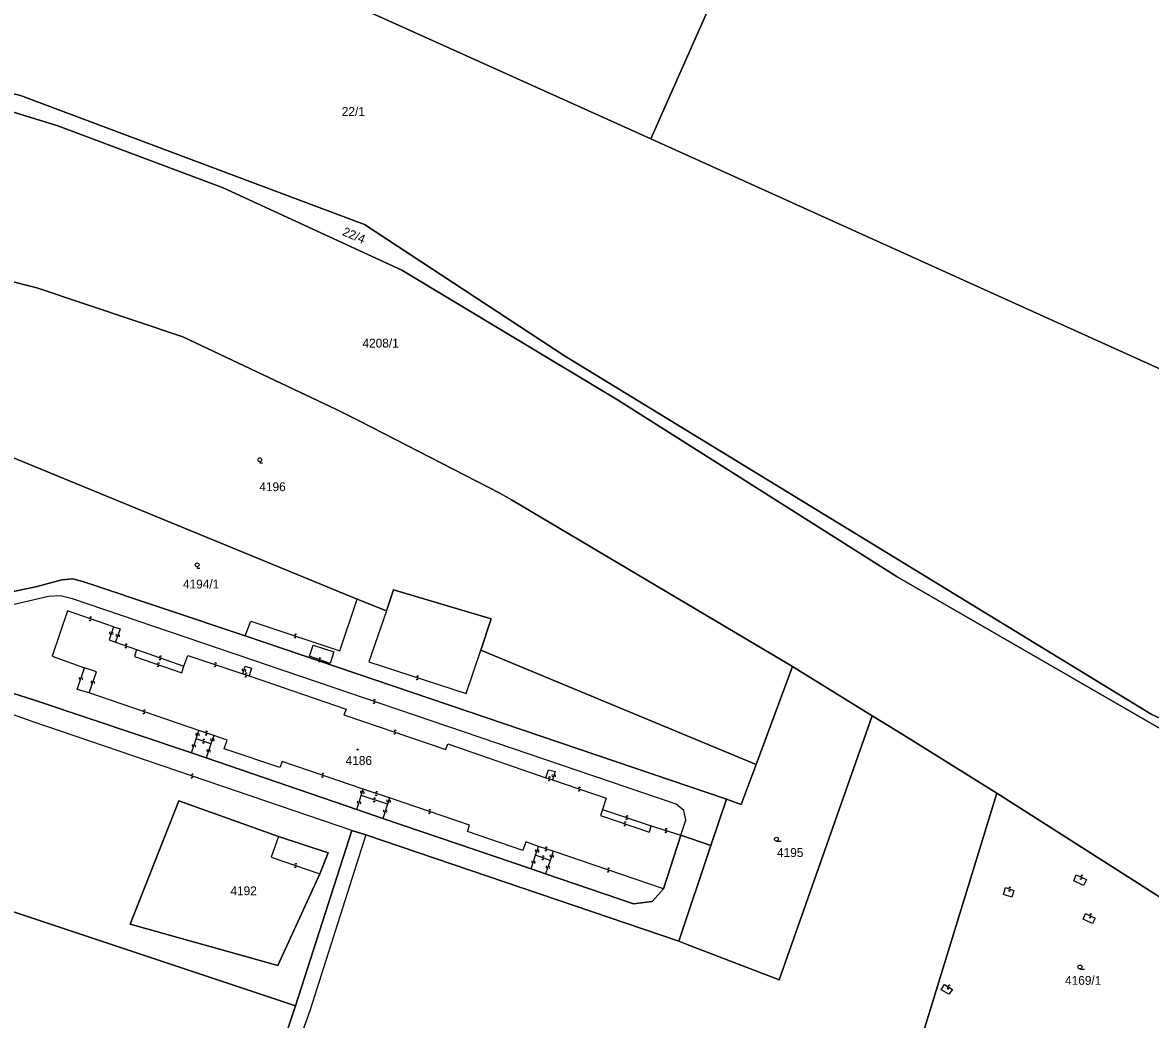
# Model space of a CAD drawing. Extents: x -598233 to -596890, y -1157848 to -1156431.
# Drawn here: x -597840.5 to -597624.3, y -1157433.9 to -1157242.7 of the extents above; entities that cross this region are included whole.
import ezdxf

# ---------------------------------------------------------------- set-up
doc = ezdxf.new("R2010")
doc.units = 0
for name, color, linetype in [('Level 1', 7, 'Continuous'), ('Level 13', 7, 'Continuous'), ('Level 3', 7, 'Continuous'), ('Level 4', 7, 'Continuous'), ('Level 5', 7, 'Continuous'), ('Level 60', 7, 'Continuous'), ('Vrstva 54', 7, 'Continuous'), ('Vrstva 60', 7, 'Continuous')]:
    doc.layers.add(name, color=color, linetype=linetype)

msp = doc.modelspace()

# ---------------------------------------------------------------- linework, layer by layer
at = {"layer": 'Level 1'}
for points in [[(-597802.39, -1157227.84), (-597776.1, -1157174.66), (-597757.16, -1157192.27), (-597734.08, -1157200.94), (-597717.33, -1157206.86), (-597697.73, -1157214.64), (-597720.07, -1157265.02)], [(-597720.07, -1157265.02), (-597802.39, -1157227.84)], [(-597939.77, -1157233.9), (-597929.67, -1157236.56), (-597923.63, -1157238.02), (-597882.54, -1157247.95), (-597875.91, -1157249.55), (-597833.74, -1157262.53), (-597802.08, -1157274.42), (-597767.8, -1157290.17), (-597726.42, -1157315.06), (-597672.84, -1157349.01), (-597621.47, -1157378.62), (-597620.65, -1157379.11), (-597584.75, -1157400.18), (-597549.68, -1157428.4), (-597544.41, -1157433.47), (-597538.53, -1157436.14), (-597519.06, -1157444.97), (-597467.58, -1157472.78), (-597426.75, -1157494.36), (-597424.47, -1157501.56)], [(-597881.96, -1157245.26), (-597876.93, -1157246.47), (-597851.3, -1157254.2), (-597840.9, -1157256.69), (-597774.98, -1157281.45), (-597736.6, -1157306.64), (-597624.12, -1157375.33), (-597619.87, -1157377.31)], [(-597882.54, -1157247.95), (-597875.91, -1157249.55), (-597833.74, -1157262.53), (-597802.08, -1157274.42), (-597767.8, -1157290.17), (-597726.42, -1157315.06), (-597672.84, -1157349.01), (-597621.47, -1157378.62), (-597620.65, -1157379.11)], [(-597594.92, -1157321.55), (-597720.07, -1157265.02)], [(-597927.09, -1157273.98), (-597877.78, -1157283.48), (-597837.79, -1157293.58), (-597809.77, -1157302.98), (-597780.3, -1157316.91), (-597775.85, -1157319.11), (-597749.01, -1157332.97), (-597746.79, -1157334.23), (-597692.89, -1157366.17)], [(-597926.42, -1157291.58), (-597776.35, -1157353.26)], [(-597876.22, -1157362.87), (-597873.55, -1157361.33), (-597870.19, -1157359.57), (-597867.07, -1157358.08), (-597864.1, -1157356.88), (-597860.64, -1157355.76), (-597857.5, -1157354.95), (-597837.95, -1157350.9), (-597832.96, -1157349.57), (-597830.88, -1157349.39), (-597828.79, -1157349.95), (-597797.85, -1157360.32)], [(-597776.35, -1157353.26), (-597770.76, -1157355.54)], [(-597770.76, -1157355.54), (-597769.38, -1157351.46), (-597750.67, -1157357.07), (-597752.67, -1157363.06)], [(-597797.85, -1157360.32), (-597705.57, -1157391.65)], [(-597752.67, -1157363.06), (-597699.85, -1157384.95)], [(-597808.11, -1157382.76), (-597838.2, -1157372.62), (-597845.13, -1157370.45), (-597867.55, -1157364.93)], [(-597699.85, -1157384.95), (-597692.89, -1157366.17)], [(-597692.89, -1157366.17), (-597677.64, -1157375.67)], [(-597677.64, -1157375.67), (-597695.43, -1157426.25), (-597712.77, -1157419.6), (-597714.69, -1157418.85)], [(-597677.64, -1157375.67), (-597672.9, -1157378.55), (-597653.75, -1157390.49)], [(-597805.31, -1157383.72), (-597808.11, -1157382.76)], [(-597776.45, -1157393.59), (-597805.31, -1157383.72)], [(-597699.85, -1157384.95), (-597702.71, -1157392.63), (-597705.57, -1157391.65)], [(-597791.44, -1157398.75), (-597810.55, -1157391.95), (-597819.87, -1157415.56), (-597791.6, -1157423.52), (-597783.54, -1157405.96)], [(-597705.57, -1157391.65), (-597708.54, -1157400.5)], [(-597667.82, -1157436.45), (-597653.75, -1157390.49)], [(-597653.75, -1157390.49), (-597620.55, -1157411.64), (-597581.5, -1157434.85), (-597556.28, -1157449.32)], [(-597771.45, -1157395.32), (-597776.45, -1157393.59)], [(-597743.02, -1157405), (-597771.45, -1157395.32)], [(-597791.44, -1157398.75), (-597781.95, -1157401.92), (-597783.54, -1157405.96)], [(-597788.17, -1157431.27), (-597777.36, -1157397.61)], [(-597774.67, -1157398.49), (-597777.36, -1157397.61)], [(-597774.67, -1157398.49), (-597714.69, -1157418.85)], [(-597714.3, -1157398.55), (-597717.66, -1157408.79)], [(-597708.54, -1157400.5), (-597714.3, -1157398.55)], [(-597708.54, -1157400.5), (-597714.69, -1157418.85)], [(-597740.24, -1157405.97), (-597743.02, -1157405)], [(-597740.24, -1157405.97), (-597723.35, -1157411.67), (-597719.83, -1157411.25), (-597717.66, -1157408.79)], [(-597788.17, -1157431.27), (-597855.38, -1157408.86)], [(-597788.17, -1157431.27), (-597800.65, -1157468.66), (-597811.31, -1157496.58)]]:
    msp.add_lwpolyline(points, dxfattribs=at)
at = {"layer": 'Level 13'}
for centre, start, end in [((-597827.57, -1157357.19), 198.2569, 70.3549), ((-597827.45, -1157356.85), 18.0424, 250.6324), ((-597823.69, -1157359.74), 109.1385, 341.7285), ((-597823.35, -1157359.86), 289.353, 161.451), ((-597822.42, -1157360.18), 108.8588, 341.4488), ((-597822.08, -1157360.3), 289.0732, 161.1712), ((-597820.62, -1157362.06), 17.4822, 249.5801), ((-597788.28, -1157360.49), 198.8138, 71.4038), ((-597788.16, -1157360.15), 19.0283, 251.1263), ((-597820.74, -1157362.4), 197.2677, 69.8577), ((-597814.07, -1157364.37), 18.2059, 250.3039), ((-597814.56, -1157366.01), 198.1016, 70.6916), ((-597814.44, -1157365.67), 18.3161, 250.4141), ((-597814.19, -1157364.71), 197.9915, 70.5815), ((-597803.63, -1157366.02), 198.5277, 71.1177), ((-597803.51, -1157365.68), 18.7421, 250.8401), ((-597783.6, -1157365.07), 198.1601, 70.2581), ((-597783.48, -1157364.73), 17.9456, 250.5356), ((-597829.51, -1157368.44), 108.7727, 340.8707), ((-597829.17, -1157368.56), 288.5582, 161.1482), ((-597798.25, -1157366.83), 109.6422, 341.7402), ((-597797.89, -1157366.95), 289.4278, 162.0178), ((-597797.74, -1157367.99), 200.5439, 73.1339), ((-597797.64, -1157367.63), 20.7583, 252.8563), ((-597764.87, -1157368.51), 199.1111, 71.7011), ((-597764.75, -1157368.17), 19.3255, 251.4235), ((-597827.2, -1157369.17), 108.3427, 340.4407), ((-597826.86, -1157369.29), 288.1283, 160.7183), ((-597773.04, -1157372.73), 18.3499, 250.9399), ((-597817.27, -1157375.03), 198.4084, 70.5064), ((-597817.15, -1157374.69), 18.194, 250.784), ((-597773.16, -1157373.07), 198.5644, 70.6624), ((-597807.12, -1157379.19), 109.1599, 341.2579), ((-597806.78, -1157379.31), 288.9454, 161.5354), ((-597805.34, -1157379.13), 198.6346, 70.7326), ((-597805.22, -1157378.79), 18.4202, 251.0102), ((-597769.18, -1157378.92), 198.3372, 70.9272), ((-597769.06, -1157378.58), 18.5516, 250.6496), ((-597807.83, -1157381.34), 108.9378, 341.0358), ((-597807.49, -1157381.46), 288.7233, 161.3133), ((-597805.86, -1157380.68), 198.5107, 70.6087), ((-597805.74, -1157380.34), 18.2962, 250.8862), ((-597804.29, -1157380.15), 108.2809, 340.8709), ((-597803.95, -1157380.27), 288.4954, 160.5934), ((-597805.02, -1157382.3), 108.5346, 341.1247), ((-597804.68, -1157382.42), 288.7491, 160.8471), ((-597808.08, -1157387.35), 198.5798, 70.6778), ((-597807.96, -1157387.01), 18.3653, 250.9553), ((-597783.03, -1157387.21), 198.4962, 70.5942), ((-597782.91, -1157386.87), 18.2818, 250.8718), ((-597739.59, -1157387.88), 200.5439, 73.1339), ((-597739.49, -1157387.52), 20.7583, 252.8563), ((-597738.84, -1157387.06), 109.2796, 341.8696), ((-597738.49, -1157387.18), 289.494, 161.592), ((-597775.56, -1157390.26), 110.7583, 342.8563), ((-597733.84, -1157389.85), 197.9901, 70.5801), ((-597733.72, -1157389.51), 18.2045, 250.3025), ((-597776.18, -1157392.2), 109.0671, 341.1651), ((-597775.84, -1157392.32), 288.8527, 161.4427), ((-597775.2, -1157390.36), 290.5439, 163.1339), ((-597773.11, -1157391.92), 199.348, 71.446), ((-597772.99, -1157391.58), 19.1336, 251.7236), ((-597772.74, -1157390.71), 198.8355, 70.9335), ((-597772.62, -1157390.37), 18.6211, 251.2111), ((-597770.52, -1157391.92), 109.8865, 342.4765), ((-597770.16, -1157392.04), 290.101, 162.199), ((-597771.16, -1157393.88), 108.6608, 341.2508), ((-597770.82, -1157394), 288.8753, 160.9733), ((-597762.54, -1157394.16), 198.6027, 70.7007), ((-597762.42, -1157393.82), 18.3883, 250.9783), ((-597725.09, -1157396.53), 198.5039, 71.0939), ((-597724.97, -1157396.19), 18.7184, 250.8164), ((-597724.72, -1157395.33), 198.7049, 71.2949), ((-597724.6, -1157394.99), 18.9193, 251.0173), ((-597717.21, -1157397.8), 199.2678, 71.8578), ((-597717.09, -1157397.46), 19.4823, 251.5803), ((-597740.1, -1157400.99), 18.8458, 251.4358), ((-597742.03, -1157401.48), 108.7346, 340.8326), ((-597741.69, -1157401.6), 288.5202, 161.1102), ((-597740.81, -1157403.05), 197.5885, 69.6865), ((-597740.69, -1157402.71), 17.374, 249.964), ((-597740.22, -1157401.33), 199.0602, 71.1582), ((-597739.23, -1157402.44), 108.3336, 340.9236), ((-597738.89, -1157402.56), 288.548, 160.646), ((-597788.24, -1157404.52), 198.0224, 70.6124), ((-597788.12, -1157404.18), 18.2368, 250.3348), ((-597742.75, -1157403.63), 108.8067, 340.9047), ((-597742.41, -1157403.75), 288.5922, 161.1822), ((-597739.97, -1157404.62), 108.3921, 340.9821), ((-597739.63, -1157404.74), 288.6066, 160.7046), ((-597728.27, -1157405.37), 198.6044, 70.7024), ((-597728.15, -1157405.03), 18.39, 250.98), ((-597637.6, -1157406.77), 193.0879, 65.6779), ((-597637.44, -1157406.43), 13.3024, 245.4004), ((-597651.33, -1157409.05), 197.7738, 70.3638), ((-597651.21, -1157408.71), 17.9882, 250.0862), ((-597635.7, -1157413.82), 11.672, 243.77), ((-597635.86, -1157414.16), 191.4575, 64.0475), ((-597663.08, -1157427.81), 185.5926, 58.1826), ((-597662.88, -1157427.49), 5.807, 237.905)]:
    msp.add_arc(centre, 0.184, start, end, dxfattribs=at)
at = {"layer": 'Level 3'}
for points in [[(-597714.3, -1157398.55), (-597713.34, -1157395.67), (-597713.73, -1157393.79), (-597715.23, -1157392.61), (-597830.97, -1157353.19), (-597833.29, -1157352.62), (-597835.57, -1157352.76), (-597856.68, -1157357.71), (-597862.88, -1157359.71), (-597868.02, -1157361.9), (-597868.88, -1157362.47), (-597869.18, -1157363.46), (-597868.86, -1157364.34), (-597867.55, -1157364.93)], [(-597797.85, -1157360.32), (-597796.77, -1157357.48), (-597779.67, -1157363.15), (-597776.35, -1157353.26)], [(-597823.11, -1157358.55), (-597831.91, -1157355.5), (-597834.84, -1157364.2), (-597828.64, -1157366.42)], [(-597770.76, -1157355.54), (-597774.14, -1157365.3), (-597755.48, -1157371.38), (-597752.67, -1157363.06)], [(-597823.11, -1157358.55), (-597823.92, -1157361.04), (-597822.67, -1157361.51)], [(-597823.11, -1157358.55), (-597821.83, -1157358.97), (-597822.67, -1157361.51)], [(-597822.67, -1157361.51), (-597818.69, -1157362.95)], [(-597818.69, -1157362.95), (-597819.04, -1157364.27), (-597809.95, -1157367.41), (-597809.57, -1157366.12)], [(-597818.69, -1157362.95), (-597809.57, -1157366.12)], [(-597809.57, -1157366.12), (-597808.84, -1157364.07), (-597798.31, -1157367.62)], [(-597784.8, -1157362.06), (-597780.86, -1157363.39), (-597781.56, -1157365.59), (-597785.52, -1157364.21), (-597784.8, -1157362.06)], [(-597798.31, -1157367.62), (-597797.84, -1157366.15), (-597796.6, -1157366.52), (-597797.07, -1157367.99)], [(-597827.73, -1157371.25), (-597830.04, -1157370.58), (-597828.64, -1157366.42)], [(-597827.73, -1157371.25), (-597826.34, -1157367.22), (-597828.64, -1157366.42)], [(-597798.31, -1157367.62), (-597797.07, -1157367.99)], [(-597797.07, -1157367.99), (-597778.49, -1157374.34), (-597778.89, -1157375.42), (-597759.35, -1157382.08), (-597758.97, -1157381), (-597740.16, -1157387.52)], [(-597806.69, -1157378.48), (-597827.73, -1157371.25)], [(-597777.36, -1157397.61), (-597838.69, -1157376.74), (-597842.27, -1157375.46)], [(-597807.2, -1157380.03), (-597806.69, -1157378.48)], [(-597803.86, -1157379.44), (-597806.69, -1157378.48)], [(-597808.11, -1157382.76), (-597807.2, -1157380.03)], [(-597804.39, -1157380.99), (-597807.2, -1157380.03)], [(-597804.39, -1157380.99), (-597805.31, -1157383.72)], [(-597803.86, -1157379.44), (-597804.39, -1157380.99)], [(-597775.2, -1157389.69), (-597790.73, -1157384.38), (-597791.19, -1157385.53), (-597801.84, -1157381.96), (-597801.27, -1157380.32), (-597803.86, -1157379.44)], [(-597740.16, -1157387.52), (-597739.68, -1157385.97), (-597738.42, -1157386.34), (-597738.92, -1157387.89)], [(-597740.16, -1157387.52), (-597738.92, -1157387.89)], [(-597738.92, -1157387.89), (-597728.65, -1157391.46), (-597729.32, -1157393.6)], [(-597775.57, -1157390.93), (-597775.2, -1157389.69)], [(-597770.16, -1157391.38), (-597775.2, -1157389.69)], [(-597776.45, -1157393.59), (-597775.57, -1157390.93)], [(-597770.53, -1157392.57), (-597775.57, -1157390.93)], [(-597770.16, -1157391.38), (-597770.53, -1157392.57)], [(-597741.57, -1157400.69), (-597744.01, -1157399.83), (-597744.6, -1157401.47), (-597755.22, -1157397.83), (-597754.8, -1157396.6), (-597770.16, -1157391.38)], [(-597770.53, -1157392.57), (-597771.45, -1157395.32)], [(-597729.32, -1157393.6), (-597729.73, -1157394.78), (-597720.34, -1157397.95), (-597720, -1157396.71)], [(-597729.32, -1157393.6), (-597720, -1157396.71)], [(-597774.67, -1157398.49), (-597785.43, -1157432.18), (-597799.88, -1157472.24), (-597820.65, -1157539.16)], [(-597791.44, -1157398.75), (-597792.82, -1157402.74), (-597783.54, -1157405.96)], [(-597720, -1157396.71), (-597714.3, -1157398.55)], [(-597742.14, -1157402.38), (-597741.57, -1157400.69)], [(-597738.76, -1157401.62), (-597741.57, -1157400.69)], [(-597743.02, -1157405), (-597742.14, -1157402.38)], [(-597739.36, -1157403.38), (-597742.14, -1157402.38)], [(-597738.76, -1157401.62), (-597739.36, -1157403.38)], [(-597717.66, -1157408.79), (-597738.76, -1157401.62)], [(-597739.36, -1157403.38), (-597740.24, -1157405.97)], [(-597638.5, -1157406.16), (-597636.53, -1157407.04), (-597637.09, -1157408.15), (-597638.96, -1157407.28), (-597638.5, -1157406.16)], [(-597652.08, -1157408.59), (-597650.46, -1157409.16), (-597650.86, -1157410.42), (-597652.46, -1157409.93), (-597652.08, -1157408.59)], [(-597636.72, -1157413.54), (-597634.85, -1157414.44), (-597635.38, -1157415.47), (-597637.17, -1157414.61), (-597636.72, -1157413.54)], [(-597663.74, -1157427.18), (-597662.21, -1157428.12), (-597662.9, -1157429.04), (-597664.38, -1157428.17), (-597663.74, -1157427.18)]]:
    msp.add_lwpolyline(points, dxfattribs=at)
at = {"layer": 'Level 5'}
for p, q in [((-597695.98, -1157399.67), (-597695.1, -1157399.67)), ((-597637.79, -1157424.19), (-597636.92, -1157424.19))]:
    msp.add_line(p, q, dxfattribs=at)
for points in [[(-597795.02, -1157326.91), (-597795.02, -1157327.16), (-597794.52, -1157327.16)], [(-597807.04, -1157347.06), (-597807.04, -1157347.31), (-597806.54, -1157347.31)]]:
    msp.add_lwpolyline(points, dxfattribs=at)
for centre, radius in [((-597795.02, -1157326.54), 0.375), ((-597807.04, -1157346.69), 0.375), ((-597776.27, -1157382.11), 0.09), ((-597776.27, -1157382.11), 0.0521), ((-597695.98, -1157399.29), 0.375), ((-597637.79, -1157423.81), 0.375)]:
    msp.add_circle(centre, radius, dxfattribs=at)
at = {"layer": 'Level 60'}
for points in [[(-597553.97, -1157115.98), (-597451.73, -1157167.37), (-597517.72, -1157209.12), (-597524.08, -1157216.07), (-597544.75, -1157236.3), (-597553.08, -1157244.43), (-597572.6, -1157270.07), (-597583.83, -1157284.82), (-597594.92, -1157321.55), (-597720.07, -1157265.02), (-597697.73, -1157214.64), (-597717.33, -1157206.86), (-597734.08, -1157200.94), (-597757.16, -1157192.27), (-597776.1, -1157174.66), (-597802.39, -1157227.84), (-597822.9, -1157218.58), (-597805.12, -1157122.39)], [(-597805.12, -1157122.39), (-597822.9, -1157218.58), (-597802.39, -1157227.84), (-597720.07, -1157265.02), (-597594.92, -1157321.55), (-597604.05, -1157339.11), (-597605.14, -1157343.41), (-597619.87, -1157377.31), (-597624.12, -1157375.33), (-597736.6, -1157306.64), (-597774.98, -1157281.45), (-597840.9, -1157256.69), (-597851.3, -1157254.2), (-597876.93, -1157246.47), (-597881.96, -1157245.26), (-597923.53, -1157235.13), (-597922.9, -1157217.48), (-597918.43, -1157192.25), (-597917.62, -1157187.34), (-597920.96, -1157183.45), (-597938.58, -1157148.02), (-597940.99, -1157134.33)], [(-597875.91, -1157249.55), (-597833.74, -1157262.53), (-597802.08, -1157274.42), (-597767.8, -1157290.17), (-597726.42, -1157315.06), (-597672.84, -1157349.01), (-597621.47, -1157378.62)], [(-597620.55, -1157411.64), (-597653.75, -1157390.49), (-597672.9, -1157378.55), (-597677.64, -1157375.67), (-597692.89, -1157366.17), (-597746.79, -1157334.23), (-597749.01, -1157332.97), (-597775.85, -1157319.11), (-597780.3, -1157316.91), (-597809.77, -1157302.98), (-597837.79, -1157293.58), (-597877.78, -1157283.48)], [(-597926.42, -1157291.58), (-597776.35, -1157353.26), (-597770.76, -1157355.54), (-597769.38, -1157351.46), (-597750.67, -1157357.07), (-597752.67, -1157363.06), (-597699.85, -1157384.95), (-597702.71, -1157392.63), (-597705.57, -1157391.65), (-597797.85, -1157360.32), (-597828.79, -1157349.95), (-597830.88, -1157349.39), (-597832.96, -1157349.57), (-597837.95, -1157350.9), (-597857.5, -1157354.95)], [(-597857.5, -1157354.95), (-597837.95, -1157350.9), (-597832.96, -1157349.57), (-597830.88, -1157349.39), (-597828.79, -1157349.95), (-597797.85, -1157360.32), (-597705.57, -1157391.65), (-597708.54, -1157400.5), (-597714.3, -1157398.55), (-597717.66, -1157408.79), (-597719.83, -1157411.25), (-597723.35, -1157411.67), (-597740.24, -1157405.97), (-597743.02, -1157405), (-597771.45, -1157395.32), (-597776.45, -1157393.59), (-597805.31, -1157383.72), (-597808.11, -1157382.76), (-597838.2, -1157372.62), (-597845.13, -1157370.45)], [(-597845.13, -1157370.45), (-597838.2, -1157372.62), (-597808.11, -1157382.76), (-597805.31, -1157383.72), (-597776.45, -1157393.59), (-597771.45, -1157395.32), (-597743.02, -1157405), (-597740.24, -1157405.97), (-597723.35, -1157411.67), (-597719.83, -1157411.25), (-597717.66, -1157408.79), (-597714.3, -1157398.55), (-597708.54, -1157400.5), (-597714.69, -1157418.85), (-597774.67, -1157398.49), (-597777.36, -1157397.61), (-597788.17, -1157431.27), (-597855.38, -1157408.86)], [(-597855.38, -1157408.86), (-597788.17, -1157431.27), (-597800.65, -1157468.66), (-597811.31, -1157496.58), (-597814.36, -1157504.63), (-597824.41, -1157537.97), (-597901.96, -1157512.06)]]:
    msp.add_lwpolyline(points, dxfattribs=at)
for points in [[(-597734.08, -1157200.94), (-597717.33, -1157206.86), (-597697.73, -1157214.64), (-597720.07, -1157265.02), (-597802.39, -1157227.84), (-597776.1, -1157174.66), (-597757.16, -1157192.27)], [(-597881.96, -1157245.26), (-597876.93, -1157246.47), (-597851.3, -1157254.2), (-597840.9, -1157256.69), (-597774.98, -1157281.45), (-597736.6, -1157306.64), (-597624.12, -1157375.33), (-597619.87, -1157377.31), (-597620.65, -1157379.11), (-597621.47, -1157378.62), (-597672.84, -1157349.01), (-597726.42, -1157315.06), (-597767.8, -1157290.17), (-597802.08, -1157274.42), (-597833.74, -1157262.53), (-597875.91, -1157249.55), (-597882.54, -1157247.95)], [(-597925.52, -1157281.09), (-597927.09, -1157273.98), (-597877.78, -1157283.48), (-597837.79, -1157293.58), (-597809.77, -1157302.98), (-597780.3, -1157316.91), (-597775.85, -1157319.11), (-597749.01, -1157332.97), (-597746.79, -1157334.23), (-597692.89, -1157366.17), (-597699.85, -1157384.95), (-597752.67, -1157363.06), (-597750.67, -1157357.07), (-597769.38, -1157351.46), (-597770.76, -1157355.54), (-597776.35, -1157353.26), (-597926.42, -1157291.58), (-597925.85, -1157288.28)], [(-597708.54, -1157400.5), (-597705.57, -1157391.65), (-597702.71, -1157392.63), (-597699.85, -1157384.95), (-597692.89, -1157366.17), (-597677.64, -1157375.67), (-597695.43, -1157426.25), (-597712.77, -1157419.6), (-597714.69, -1157418.85)], [(-597777.36, -1157397.61), (-597774.67, -1157398.49), (-597714.69, -1157418.85), (-597712.77, -1157419.6), (-597695.43, -1157426.25), (-597677.64, -1157375.67), (-597672.9, -1157378.55), (-597653.75, -1157390.49), (-597667.82, -1157436.45), (-597669.37, -1157441.52), (-597692.09, -1157436.77), (-597710.38, -1157490.66), (-597729.96, -1157487.59), (-597792.76, -1157466.57), (-597796.51, -1157477.25), (-597818.67, -1157539.87), (-597820.65, -1157539.16), (-597824.41, -1157537.97), (-597814.36, -1157504.63), (-597811.31, -1157496.58), (-597800.65, -1157468.66), (-597788.17, -1157431.27)], [(-597791.44, -1157398.75), (-597810.55, -1157391.95), (-597819.87, -1157415.56), (-597791.6, -1157423.52), (-597783.54, -1157405.96), (-597781.95, -1157401.92)], [(-597810.55, -1157391.95), (-597791.44, -1157398.75), (-597781.95, -1157401.92), (-597783.54, -1157405.96), (-597791.6, -1157423.52), (-597819.87, -1157415.56)], [(-597593.31, -1157473.31), (-597628.63, -1157449.57), (-597639.6, -1157447.4), (-597667.82, -1157436.45), (-597653.75, -1157390.49), (-597620.55, -1157411.64), (-597581.5, -1157434.85), (-597556.28, -1157449.32), (-597566.34, -1157462.32), (-597571.24, -1157468.5), (-597579.81, -1157466.73), (-597582.64, -1157480.48)]]:
    msp.add_lwpolyline(points, close=True, dxfattribs=at)
at = {"layer": 'Vrstva 54'}
for p, q in [((-597875.91, -1157249.55), (-597833.74, -1157262.53)), ((-597833.74, -1157262.53), (-597802.08, -1157274.42)), ((-597802.08, -1157274.42), (-597767.8, -1157290.17)), ((-597767.8, -1157290.17), (-597726.42, -1157315.06)), ((-597726.42, -1157315.06), (-597672.84, -1157349.01)), ((-597672.84, -1157349.01), (-597621.47, -1157378.62))]:
    msp.add_line(p, q, dxfattribs=at)
at = {"layer": 'Vrstva 60'}
for points in [[(-597977.93, -1157142.48), (-597982.59, -1157147.71), (-597981.47, -1157149.61), (-597971.72, -1157166.16), (-597970.17, -1157171.99), (-597968.92, -1157171.76), (-597955.98, -1157197.6), (-597952.02, -1157203.83), (-597943.32, -1157225.19), (-597941, -1157230.87), (-597939.77, -1157233.9), (-597929.67, -1157236.56), (-597923.63, -1157238.02), (-597882.54, -1157247.95), (-597875.91, -1157249.55), (-597833.74, -1157262.53), (-597802.08, -1157274.42), (-597767.8, -1157290.17), (-597726.42, -1157315.06), (-597672.84, -1157349.01), (-597621.47, -1157378.62)], [(-597621.47, -1157378.62), (-597672.84, -1157349.01), (-597726.42, -1157315.06), (-597767.8, -1157290.17), (-597802.08, -1157274.42), (-597833.74, -1157262.53), (-597875.91, -1157249.55), (-597882.54, -1157247.95), (-597923.63, -1157238.02), (-597929.67, -1157236.56), (-597939.77, -1157233.9), (-597941, -1157230.87), (-597943.32, -1157225.19), (-597952.02, -1157203.83), (-597955.98, -1157197.6), (-597968.92, -1157171.76), (-597970.17, -1157171.99), (-597971.72, -1157166.16), (-597981.47, -1157149.61), (-597982.59, -1157147.71), (-597977.93, -1157142.48)]]:
    msp.add_lwpolyline(points, dxfattribs=at)

# ---------------------------------------------------------------- texts
at = {"layer": 'Level 4'}
for s, p in [('22/1', (-597779.31, -1157260.61)), ('4208/1', (-597775.34, -1157305.03)), ('4196', (-597795.12, -1157332.56)), ('4194/1', (-597809.76, -1157351.22)), ('4186', (-597778.57, -1157385.06)), ('4195', (-597695.87, -1157402.71)), ('4192', (-597800.66, -1157410.04)), ('4169/1', (-597640.64, -1157427.22))]:
    msp.add_text(s, height=1.7, dxfattribs=at).set_placement(p)
msp.add_text('22/4', height=1.7, rotation=337.3923, dxfattribs=at).set_placement((-597779.34, -1157283.43))

doc.saveas('drawing.dxf')
